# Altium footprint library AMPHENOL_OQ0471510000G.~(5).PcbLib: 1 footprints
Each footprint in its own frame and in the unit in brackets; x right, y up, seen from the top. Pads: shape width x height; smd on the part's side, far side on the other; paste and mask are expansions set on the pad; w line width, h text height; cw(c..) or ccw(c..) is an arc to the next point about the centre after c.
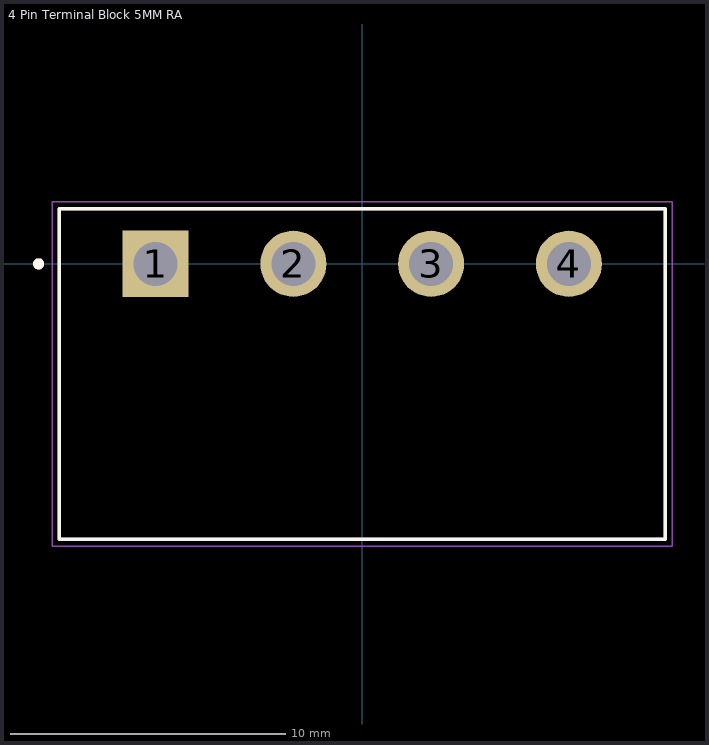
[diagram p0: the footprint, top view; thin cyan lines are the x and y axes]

## 4 Pin Terminal Block 5MM RA [mm] "4 Pin Terminal Block HDR 5MM THT RA OQ0471510000G"
pads (4):
  rect 2.4x2.4 hole 1.6: 1(-7.5,0)
  round 2.4 hole 1.6: 2(-2.5,0) 3(2.5,0) 4(7.5,0)
Top Overlay:
  circle w0.2: c-11.75,0 r0.1
  lines w0.127: -11,-10 11,-10 11,2 -11,2 -11,-10
Mechanical 13:
  circle w0.2: c-11.75,0 r0.1
  lines w0.127: -11,-10 11,-10 11,2 -11,2 -11,-10
Mechanical 15:
  lines w0.05: -11.25,-10.25 11.25,-10.25 11.25,2.25 -11.25,2.25 -11.25,-10.25
3D body "796700-4--3DModel-STEP-510211.STEP": height 8.5, standoff -3.5, extent -11.254,-10.064 10.746,1.936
